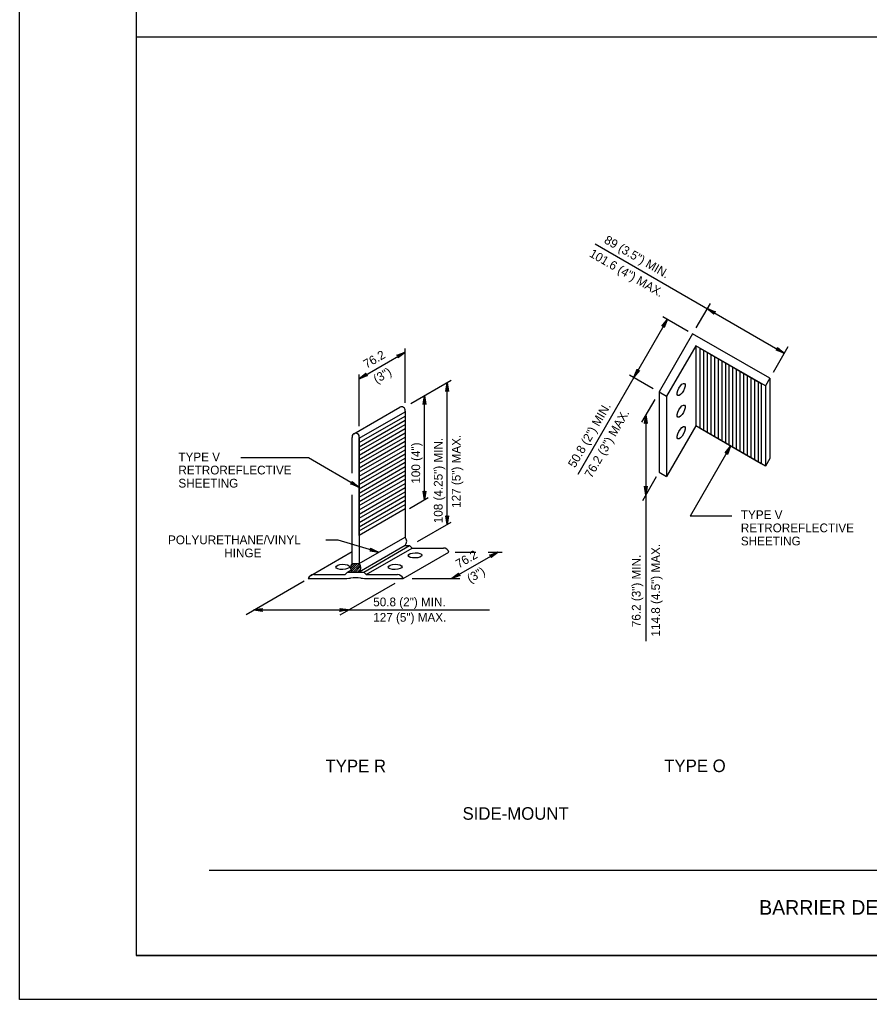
# Model space of a CAD drawing. Extents: x 640253 to 641999, y 298458 to 299646.
# Drawn here: x 640253.3 to 640544.6, y 298457.6 to 298793.5 of the extents above; entities that cross this region are included whole.
import ezdxf

# ---------------------------------------------------------------- set-up
doc = ezdxf.new("R2010")
doc.units = 0
for name, color, linetype in [('1', 7, 'Continuous'), ('2', 7, 'Continuous'), ('PLT-BNDY', 7, 'Continuous')]:
    doc.layers.add(name, color=color, linetype=linetype)

msp = doc.modelspace()

# ---------------------------------------------------------------- linework, layer by layer
at = {"layer": '1'}
for p, q in [((640293.31, 299036.63), (640293.31, 298472.63)), ((640293.31, 298787.67), (641079.31, 298787.67)), ((640318.26, 298501.97), (640782.88, 298501.97)), ((641079.31, 298472.63), (640293.31, 298472.63)), ((640293.31, 298472.63), (640879.31, 298472.63))]:
    msp.add_line(p, q, dxfattribs=at)
at = {"layer": '2'}
for p, q in [((640450.56, 298716.64), (640515.45, 298679.17)), ((640489.99, 298696.18), (640485.17, 298687.84)), ((640475.38, 298690.81), (640444.63, 298637.55)), ((640473.86, 298691.69), (640482.49, 298686.7)), ((640484.01, 298685.83), (640472.51, 298665.91)), ((640510.48, 298670.55), (640484.01, 298685.83)), ((640369.76, 298670.43), (640385.5, 298679.52)), ((640385.5, 298662.1), (640385.5, 298680.83)), ((640485.11, 298681.73), (640475.11, 298664.41)), ((640508.98, 298667.95), (640485.11, 298681.73)), ((640485.11, 298681.73), (640485.11, 298654.23)), ((640487.74, 298680.21), (640487.74, 298652.71)), ((640488.99, 298679.49), (640488.99, 298651.99)), ((640516.7, 298681.32), (640511.64, 298672.56)), ((640490.24, 298678.77), (640490.24, 298651.27)), ((640491.49, 298678.05), (640491.49, 298650.55)), ((640492.74, 298677.32), (640492.74, 298649.83)), ((640493.99, 298676.6), (640493.99, 298649.1)), ((640495.24, 298675.88), (640495.24, 298648.38)), ((640496.49, 298675.16), (640496.49, 298647.66)), ((640497.74, 298674.44), (640497.74, 298646.94)), ((640498.99, 298673.72), (640498.99, 298646.22)), ((640500.24, 298672.99), (640500.24, 298645.5)), ((640369.76, 298654.18), (640369.76, 298671.9)), ((640387.48, 298661.95), (640401.21, 298669.87)), ((640462.36, 298671.77), (640470.52, 298667.06)), ((640501.49, 298672.27), (640501.49, 298644.77)), ((640502.74, 298671.55), (640502.74, 298644.05)), ((640503.99, 298670.83), (640503.99, 298643.33)), ((640505.24, 298670.11), (640505.24, 298642.61)), ((640506.49, 298669.38), (640506.49, 298641.89)), ((640510.48, 298670.55), (640508.98, 298667.95)), ((640510.48, 298670.55), (640510.48, 298643.05)), ((640399.85, 298620.44), (640399.85, 298669.09)), ((640508.98, 298667.95), (640508.98, 298640.45)), ((640392.09, 298628.92), (640392.09, 298664.61)), ((640471.02, 298663.32), (640466.52, 298655.53)), ((640472.51, 298665.91), (640475.11, 298664.41)), ((640472.51, 298665.91), (640472.51, 298638.41)), ((640475.11, 298664.41), (640475.11, 298636.91)), ((640367.87, 298651.54), (640383.62, 298660.63)), ((640385.5, 298659.34), (640385.5, 298616.13)), ((640369.76, 298648.55), (640385.5, 298657.63)), ((640369.76, 298647.1), (640385.5, 298656.19)), ((640467.96, 298658.03), (640467.96, 298580.49)), ((640369.76, 298645.66), (640385.5, 298654.75)), ((640369.76, 298644.22), (640385.5, 298653.3)), ((640485.11, 298654.23), (640475.11, 298636.91)), ((640508.98, 298640.45), (640485.11, 298654.23)), ((640367.26, 298637.98), (640367.26, 298650.25)), ((640369.76, 298642.77), (640385.5, 298651.86)), ((640369.76, 298641.33), (640385.5, 298650.42)), ((640369.76, 298650.25), (640369.76, 298607.04)), ((640369.76, 298649.71), (640369.99, 298650.11)), ((640369.76, 298649.75), (640369.95, 298650.09)), ((640369.76, 298639.89), (640385.5, 298648.97)), ((640369.76, 298638.44), (640385.5, 298647.53)), ((640369.76, 298637), (640385.5, 298646.09)), ((640497.06, 298647.33), (640483.19, 298623.3)), ((640352.35, 298643.33), (640329.11, 298643.33)), ((640369.63, 298633.22), (640352.35, 298643.33)), ((640369.76, 298635.56), (640385.5, 298644.64)), ((640369.76, 298634.11), (640385.5, 298643.2)), ((640510.48, 298643.05), (640508.98, 298640.45)), ((640369.76, 298632.67), (640385.5, 298641.76)), ((640369.76, 298631.22), (640385.5, 298640.31)), ((640369.76, 298629.78), (640385.5, 298638.87)), ((640369.76, 298628.34), (640385.5, 298637.43)), ((640369.76, 298626.9), (640385.5, 298635.98)), ((640471.54, 298636.74), (640466.84, 298628.59)), ((640472.51, 298638.41), (640475.11, 298636.91)), ((640369.76, 298625.45), (640385.5, 298634.54)), ((640369.76, 298624.01), (640385.5, 298633.1)), ((640367.26, 298607.04), (640367.26, 298630.65)), ((640369.76, 298622.56), (640385.5, 298631.65)), ((640369.76, 298621.12), (640385.5, 298630.21)), ((640386.97, 298625.96), (640393.4, 298629.67)), ((640369.76, 298619.68), (640385.5, 298628.77)), ((640369.76, 298618.24), (640385.5, 298627.32)), ((640497.44, 298623.3), (640483.19, 298623.3)), ((640389.66, 298614.56), (640401.21, 298621.22)), ((640369.76, 298607.04), (640385.5, 298616.13)), ((640362.57, 298615.03), (640358.24, 298615.03)), ((640376.36, 298610.99), (640362.57, 298615.03)), ((640385.5, 298613.24), (640369.76, 298604.15)), ((640371.26, 298604.15), (640387, 298613.24)), ((640372.13, 298603.27), (640387.88, 298612.37)), ((640385.5, 298613.24), (640387, 298613.24)), ((640387, 298613.24), (640387.88, 298612.37)), ((640387.88, 298612.37), (640398.6, 298612.37)), ((640353.17, 298603.01), (640367.26, 298611.14)), ((640384.75, 298601.9), (640400.5, 298610.99)), ((640401.49, 298601.9), (640417.25, 298610.99)), ((640402.58, 298610.99), (640409.67, 298610.99)), ((640413.99, 298610.99), (640418.79, 298610.99)), ((640366.78, 298605.37), (640368.45, 298607.04)), ((640366.85, 298606.14), (640367.74, 298607.04)), ((640366.91, 298604.79), (640369.16, 298607.04)), ((640367.14, 298604.32), (640369.8, 298606.97)), ((640367.26, 298607.04), (640369.76, 298607.04)), ((640367.68, 298604.15), (640370.07, 298606.54)), ((640368.39, 298604.15), (640370.22, 298605.99)), ((640354.16, 298603.27), (640364.88, 298603.27)), ((640365.76, 298604.15), (640364.88, 298603.27)), ((640365.76, 298604.15), (640366.88, 298604.8)), ((640365.76, 298604.15), (640371.26, 298604.15)), ((640369.1, 298604.15), (640370.23, 298605.29)), ((640369.76, 298604.15), (640369.76, 298604.15)), ((640371.26, 298604.15), (640372.13, 298603.27)), ((640372.13, 298603.27), (640382.85, 298603.27)), ((640331.01, 298589.63), (640350.88, 298601.1)), ((640352.26, 298601.9), (640364.16, 298601.9)), ((640363.15, 298589.43), (640382.07, 298600.35)), ((640372.86, 298601.9), (640384.75, 298601.9)), ((640387.83, 298601.9), (640404.22, 298601.9)), ((640333.6, 298591.13), (640414.34, 298591.13))]:
    msp.add_line(p, q, dxfattribs=at)
for points in [[(640491.28, 298692.71), (640491.29, 298692.94), (640488.99, 298694.45), (640491.28, 298692.71), (640491.35, 298692.53), (640488.99, 298694.45), (640491.44, 298693.19), (640491.62, 298693.32), (640488.99, 298694.45), (640491.83, 298693.36), (640491.62, 298693.32)], [(640473.64, 298688.52), (640473.87, 298688.51), (640475.38, 298690.81), (640473.64, 298688.52), (640473.46, 298688.46), (640475.38, 298690.81), (640474.12, 298688.37), (640474.25, 298688.18), (640475.38, 298690.81), (640474.29, 298687.98), (640474.25, 298688.18)], [(640382.85, 298678.41), (640383.04, 298678.28), (640385.5, 298679.52), (640382.85, 298678.41), (640382.66, 298678.44), (640385.5, 298679.52), (640383.19, 298678.03), (640383.2, 298677.81), (640385.5, 298679.52), (640383.14, 298677.61), (640383.2, 298677.81)], [(640513.16, 298680.91), (640513.15, 298680.68), (640515.45, 298679.17), (640513.16, 298680.91), (640513.1, 298681.09), (640515.45, 298679.17), (640513.01, 298680.43), (640512.82, 298680.3), (640515.45, 298679.17), (640512.62, 298680.26), (640512.82, 298680.3)], [(640465.62, 298673.19), (640465.38, 298673.2), (640463.88, 298670.9), (640465.62, 298673.19), (640465.8, 298673.25), (640463.88, 298670.9), (640465.13, 298673.34), (640465.01, 298673.53), (640463.88, 298670.9), (640464.97, 298673.73), (640465.01, 298673.53)], [(640372.41, 298671.55), (640372.21, 298671.68), (640369.76, 298670.43), (640372.41, 298671.55), (640372.6, 298671.52), (640369.76, 298670.43), (640372.07, 298671.92), (640372.05, 298672.15), (640369.76, 298670.43), (640372.12, 298672.35), (640372.05, 298672.15)], [(640399.5, 298666.24), (640399.7, 298666.34), (640399.85, 298669.09), (640399.5, 298666.24), (640399.37, 298666.09), (640399.85, 298669.09), (640399.99, 298666.35), (640400.19, 298666.25), (640399.85, 298669.09), (640400.33, 298666.09), (640400.19, 298666.25)], [(640391.74, 298661.76), (640391.94, 298661.86), (640392.09, 298664.61), (640391.74, 298661.76), (640391.61, 298661.61), (640392.09, 298664.61), (640392.23, 298661.86), (640392.43, 298661.76), (640392.09, 298664.61), (640392.57, 298661.61), (640392.43, 298661.76)], [(640467.6, 298655.18), (640467.81, 298655.29), (640467.96, 298658.03), (640467.6, 298655.18), (640467.48, 298655.03), (640467.96, 298658.03), (640468.1, 298655.29), (640468.3, 298655.19), (640467.96, 298658.03), (640468.44, 298655.03), (640468.3, 298655.19)], [(640495.33, 298645.04), (640495.56, 298645.03), (640497.06, 298647.33), (640495.33, 298645.04), (640495.15, 298644.97), (640497.06, 298647.33), (640495.81, 298644.88), (640495.94, 298644.7), (640497.06, 298647.33), (640495.98, 298644.49), (640495.94, 298644.7)], [(640367.36, 298634.99), (640367.34, 298634.76), (640369.63, 298633.22), (640367.36, 298634.99), (640367.3, 298635.17), (640369.63, 298633.22), (640367.2, 298634.51), (640367.01, 298634.38), (640369.63, 298633.22), (640366.8, 298634.35), (640367.01, 298634.38)], [(640468.32, 298633.39), (640468.11, 298633.28), (640467.96, 298630.53), (640468.32, 298633.39), (640468.45, 298633.53), (640467.96, 298630.53), (640467.83, 298633.28), (640467.62, 298633.38), (640467.96, 298630.53), (640467.49, 298633.53), (640467.62, 298633.38)], [(640392.45, 298631.77), (640392.25, 298631.66), (640392.09, 298628.92), (640392.45, 298631.77), (640392.58, 298631.92), (640392.09, 298628.92), (640391.96, 298631.66), (640391.75, 298631.76), (640392.09, 298628.92), (640391.62, 298631.92), (640391.75, 298631.76)], [(640400.21, 298623.29), (640400.01, 298623.19), (640399.85, 298620.44), (640400.21, 298623.29), (640400.34, 298623.44), (640399.85, 298620.44), (640399.72, 298623.19), (640399.51, 298623.29), (640399.85, 298620.44), (640399.38, 298623.44), (640399.51, 298623.29)], [(640373.72, 298612.13), (640373.77, 298611.9), (640376.36, 298610.99), (640373.72, 298612.13), (640373.62, 298612.29), (640376.36, 298610.99), (640373.69, 298611.62), (640373.54, 298611.45), (640376.36, 298610.99), (640373.35, 298611.37), (640373.54, 298611.45)], [(640414.6, 298609.88), (640414.79, 298609.75), (640417.25, 298610.99), (640414.6, 298609.88), (640414.41, 298609.91), (640417.25, 298610.99), (640414.94, 298609.5), (640414.95, 298609.28), (640417.25, 298610.99), (640414.89, 298609.08), (640414.95, 298609.28)], [(640404.14, 298603.02), (640403.95, 298603.14), (640401.49, 298601.9), (640404.14, 298603.02), (640404.33, 298602.98), (640401.49, 298601.9), (640403.8, 298603.39), (640403.79, 298603.62), (640401.49, 298601.9), (640403.85, 298603.81), (640403.79, 298603.62)], [(640336.46, 298590.77), (640336.35, 298590.98), (640333.6, 298591.13), (640336.46, 298590.77), (640336.6, 298590.65), (640333.6, 298591.13), (640336.35, 298591.26), (640336.45, 298591.47), (640333.6, 298591.13), (640336.6, 298591.61), (640336.45, 298591.47)], [(640363.24, 298591.49), (640363.34, 298591.28), (640366.09, 298591.13), (640363.24, 298591.49), (640363.09, 298591.61), (640366.09, 298591.13), (640363.35, 298590.99), (640363.25, 298590.79), (640366.09, 298591.13), (640363.09, 298590.65), (640363.25, 298590.79)]]:
    msp.add_lwpolyline(points, dxfattribs=at)
for points in [[(640486.61, 298680.87), (640507.52, 298668.79), (640507.52, 298641.29), (640486.61, 298653.37)], [(640369.76, 298616.71), (640369.76, 298649.98), (640385.5, 298659.07), (640385.5, 298625.8)]]:
    msp.add_lwpolyline(points, close=True, dxfattribs=at)
for centre, radius, start, end in [((640384.25, 298659.54), 1.26, 350.9133, 119.9792), ((640368.51, 298650.45), 1.26, 350.9133, 189.0867), ((640383.72, 298614.69), 2.29, 320.9923, 39.0623), ((640398.6, 298610.37), 2, 18.187, 90), ((640369.04, 298605.59), 2.29, 140.9377, 219.0623), ((640367.98, 298605.59), 2.29, 320.9923, 39.0623), ((640354.16, 298601.27), 2, 90, 161.79), ((640368.51, 298589.7), 12.5, 81.9962, 98.0038), ((640382.85, 298601.27), 2, 18.21, 90), ((640364.16, 298620.65), 18.75, 270, 278.0038), ((640372.86, 298620.65), 18.75, 261.9962, 270)]:
    msp.add_arc(centre, radius, start, end, dxfattribs=at)
for centre, major_axis in [((640480.11, 298666.73), (-1.14, -2.07)), ((640480.11, 298659.32), (-1.14, -2.07)), ((640480.11, 298651.91), (-1.14, -2.07)), ((640388.88, 298609.85), (2.36, 0.05)), ((640364.07, 298605.9), (2.36, 0.05)), ((640382.04, 298605.9), (2.36, 0.05))]:
    msp.add_ellipse(centre, major_axis=major_axis, ratio=0.379302, dxfattribs=at)
at = {"layer": 'PLT-BNDY'}
msp.add_lwpolyline([(640253.31, 299051.63), (641094.31, 299051.63), (641094.31, 298457.63), (640253.31, 298457.63)], close=True, dxfattribs=at)

# ---------------------------------------------------------------- texts
at = {"layer": '2'}
for s, rotation, p in [('89 (3.5") MIN.', 329.9989, (640453.42, 298717.12)), ('101.6 (4") MAX.', 329.9989, (640448.35, 298712.48)), ('76.2', 30, (640372.23, 298673.85)), ('(3")', 30, (640375.67, 298668.7)), ('50.8 (2") MIN.', 59.9989, (640443.7, 298639.64)), ('76.2 (3") MAX.', 59.9989, (640449.38, 298636.13)), ('108 (4.25") MIN.', 90, (640398.32, 298620.87)), ('127 (5") MAX.', 90, (640404.48, 298626.13)), ('100 (4")', 90, (640390.62, 298634.43)), ('114.8 (4.5") MAX.', 89.9989, (640472.83, 298582.03)), ('76.2', 30, (640403.87, 298605.32)), ('76.2 (3") MIN.', 89.9989, (640466.19, 298585.24)), ('(3")', 30, (640407.75, 298600.32))]:
    msp.add_text(s, height=3, rotation=rotation, dxfattribs=at).set_placement(p)
for s, height, p in [('TYPE V', 3, (640307.75, 298642.1)), ('RETROREFLECTIVE', 3, (640307.75, 298637.6)), ('SHEETING', 3, (640307.75, 298633.1)), ('TYPE V', 3, (640500.55, 298622.28)), ('RETROREFLECTIVE', 3, (640500.55, 298617.78)), ('POLYURETHANE/VINYL', 3, (640304.2, 298613.68)), ('SHEETING', 3, (640500.55, 298613.28)), ('HINGE', 3, (640323.48, 298609.18)), ('50.8 (2") MIN.', 3, (640374.54, 298592.39)), ('127 (5") MAX.', 3, (640374.54, 298587.11)), ('TYPE R', 4.3, (640358.16, 298535.5)), ('TYPE O', 4.3, (640474.27, 298535.56)), ('SIDE-MOUNT', 4.3, (640405.14, 298519.22)), ('BARRIER DELINEATORS', 5, (640506.83, 298486.66))]:
    msp.add_text(s, height=height, dxfattribs=at).set_placement(p)

doc.saveas('drawing.dxf')
